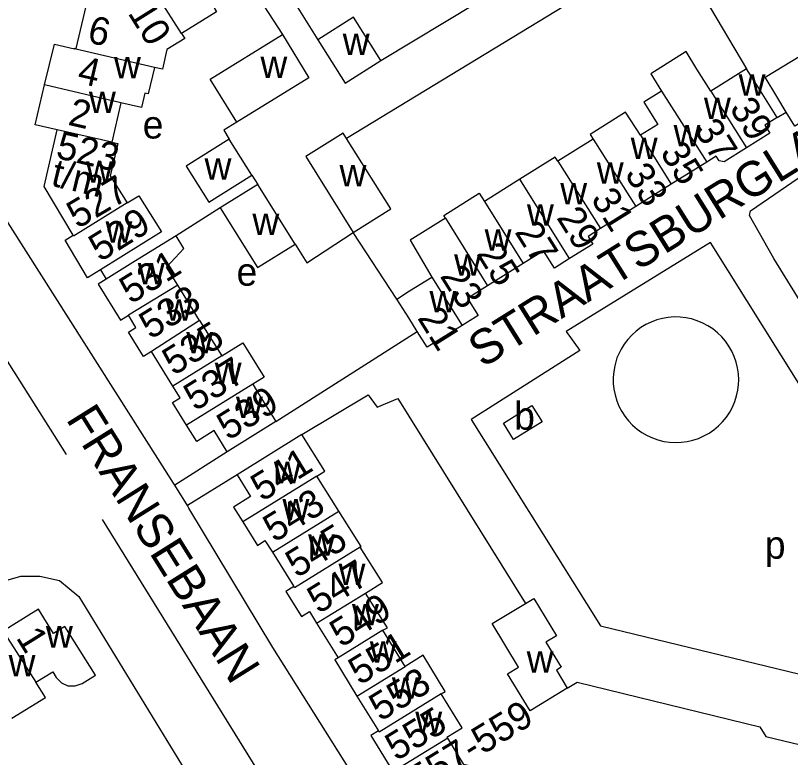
# Model space of a CAD drawing. Extents: x 157768 to 159790, y 387230 to 389604.
# Drawn here: x 158584.9 to 158696.4, y 388182.9 to 388289.6 of the extents above; entities that cross this region are included whole.
import ezdxf

# ---------------------------------------------------------------- set-up
doc = ezdxf.new("R2010")
doc.units = 0
for name, color, linetype in [('BLT_Basislijn', 7, 'Continuous'), ('BLT_Bebouwing', 7, 'Continuous'), ('BLT_Centroide', 7, 'Continuous'), ('BLT_Huisnummer', 7, 'Continuous'), ('BLT_Huisnummer_ tussenligend', 7, 'Continuous'), ('BLT_Huisnummer_reeks', 7, 'Continuous'), ('BLT_Onderverdeling_panden', 7, 'Continuous'), ('BLT_Straatnaam', 7, 'Continuous')]:
    doc.layers.add(name, color=color, linetype=linetype)

msp = doc.modelspace()

# ---------------------------------------------------------------- linework, layer by layer
at = {"layer": 'BLT_Basislijn'}
for p, q in [((158679.85, 388299.15), (158690.09, 388281.99)), ((158560.15, 388277.18), (158592.15, 388226.46)), ((158694.5, 388274.97), (158695.78, 388275.75)), ((158618.9, 388266.66), (158619.73, 388265.33)), ((158614.34, 388261.95), (158607.98, 388257.93)), ((158639.76, 388248.84), (158633.48, 388258.43)), ((158597.1, 388253.04), (158597.91, 388251.68)), ((158622.36, 388231.21), (158642.7, 388244.15)), ((158615.35, 388226.86), (158607.81, 388222.05)), ((158616.77, 388223.53), (158609.61, 388219.13)), ((158609.61, 388219.13), (158607.81, 388222.05)), ((158626.55, 388170.08), (158597.38, 388217.11))]:
    msp.add_line(p, q, dxfattribs=at)
for points in [[(158607.81, 388222.05), (158607.62, 388222.36), (158573.53, 388275.96), (158571.82, 388280.08), (158571.88, 388282.31), (158574.07, 388285.57), (158609.87, 388308.08)], [(158637.44, 388283.15), (158665.18, 388299.91), (158667.07, 388300.37), (158668.76, 388297.71), (158670.16, 388294.85), (158632.51, 388271.94)], [(158618.57, 388294.26), (158623.28, 388286.89)], [(158622.89, 388295.03), (158628.39, 388286.15)], [(158616.72, 388274.31), (158614.84, 388273.15), (158615.64, 388271.86)], [(158706.07, 388235.18), (158705.48, 388236.13), (158693.99, 388254.66), (158690.52, 388260.86), (158690.65, 388261.55), (158700.1, 388268.01)], [(158625.11, 388256.76), (158626.8, 388254.07), (158633.48, 388258.43)], [(158666.08, 388241.43), (158650.47, 388231.51), (158669.07, 388201.82), (158708.81, 388192.17), (158720.79, 388199.72), (158684.89, 388256.97)], [(158684.89, 388256.97), (158664.12, 388244.17), (158666.08, 388241.43)], [(158688.95, 388237.22), (158688.91, 388238.07), (158688.79, 388238.92), (158688.6, 388239.74), (158688.32, 388240.55), (158687.97, 388241.32), (158687.55, 388242.06), (158687.06, 388242.76), (158686.51, 388243.4), (158685.9, 388243.99), (158685.24, 388244.53), (158684.53, 388244.99), (158683.78, 388245.39), (158682.99, 388245.72), (158682.18, 388245.97), (158681.35, 388246.15), (158680.51, 388246.24), (158679.66, 388246.26), (158678.81, 388246.19), (158677.97, 388246.05), (158677.15, 388245.83), (158676.35, 388245.53), (158675.59, 388245.16), (158674.86, 388244.72), (158674.18, 388244.21), (158673.55, 388243.64), (158672.98, 388243.01), (158672.46, 388242.34), (158672.02, 388241.61), (158671.43, 388240.39)], [(158671.43, 388240.39), (158671.11, 388239.24), (158670.96, 388238.4), (158670.88, 388237.55), (158670.89, 388236.7), (158670.98, 388235.86), (158671.15, 388235.03), (158671.4, 388234.21), (158671.72, 388233.42), (158672.11, 388232.67), (158672.57, 388231.96), (158673.1, 388231.29), (158673.69, 388230.68), (158674.33, 388230.12), (158675.02, 388229.63), (158675.76, 388229.2), (158676.53, 388228.85), (158677.33, 388228.56), (158678.16, 388228.36), (158679, 388228.23), (158679.85, 388228.19), (158680.7, 388228.22), (158681.54, 388228.33), (158682.37, 388228.53), (158683.17, 388228.79), (158683.95, 388229.14), (158684.69, 388229.55), (158685.39, 388230.03), (158686.04, 388230.58), (158686.64, 388231.18), (158687.18, 388231.84), (158687.65, 388232.55), (158688.06, 388233.3), (158688.39, 388234.08), (158688.65, 388234.89), (158688.83, 388235.72), (158688.93, 388236.56), (158688.95, 388237.22)], [(158626.09, 388229.33), (158635.62, 388235.07), (158636.92, 388233.29), (158639.89, 388234.54), (158658.26, 388205.03)], [(158754.91, 388212.48), (158768.65, 388190.46), (158771.84, 388184.46), (158771.68, 388182.61), (158768.32, 388179.87), (158719.99, 388149.59), (158716.6, 388147.54), (158715.16, 388147.58), (158654.55, 388162.64), (158646.18, 388166.5), (158640.59, 388170.73), (158635.71, 388176.23), (158633.8, 388179.81), (158621.93, 388198.67), (158609.83, 388218.76), (158609.61, 388219.13)], [(158664.28, 388192.84), (158665.72, 388193.71), (158692.01, 388187.29), (158692.87, 388185.9), (158706.22, 388182.68), (158706.92, 388182.64), (158754.91, 388212.48)], [(158555.78, 388190.95), (158583.17, 388208.25), (158585.63, 388208.98), (158588.36, 388208.98), (158591.21, 388208.32), (158593.97, 388206.02), (158608.79, 388181.84), (158609.35, 388180.91)]]:
    msp.add_lwpolyline(points, dxfattribs=at)
at = {"layer": 'BLT_Bebouwing'}
for p, q in [((158690.09, 388281.99), (158684.94, 388278.76)), ((158618.9, 388266.66), (158615.64, 388271.86)), ((158668, 388271.87), (158662.91, 388268.68)), ((158684.34, 388268.56), (158679.25, 388265.37)), ((158619.73, 388265.33), (158614.34, 388261.95)), ((158625.11, 388256.76), (158619.73, 388265.33)), ((158679.25, 388265.37), (158674.16, 388262.18)), ((158674.16, 388262.18), (158669.07, 388258.99)), ((158657.94, 388253.96), (158652.78, 388250.72)), ((158611.38, 388245.75), (158614.55, 388240.65)), ((158607.52, 388236.29), (158604.43, 388241.28)), ((158622.36, 388231.21), (158615.35, 388226.86)), ((158626.09, 388229.33), (158616.77, 388223.53)), ((158631.41, 388218.29), (158628.23, 388223.37)), ((158634.6, 388213.21), (158631.41, 388218.29)), ((158621.84, 388212.39), (158624.93, 388207.46)), ((158628.2, 388202.21), (158631.3, 388197.21)), ((158640.97, 388195.97), (158637.76, 388201.18)), ((158634.02, 388191.71), (158637.1, 388186.7))]:
    msp.add_line(p, q, dxfattribs=at)
for points in [[(158593.35, 388284.85), (158593.38, 388284.96), (158593.62, 388284.91), (158595.46, 388292.86), (158602.3, 388297.17)], [(158613.32, 388290.97), (158613.8, 388290.19), (158608.79, 388287.06)], [(158637.44, 388283.15), (158633.53, 388289.39), (158628.39, 388286.15)], [(158608.79, 388287.06), (158609.24, 388286.35), (158606.67, 388284.75), (158606.02, 388281.91), (158604.87, 388282.18)], [(158616.72, 388274.31), (158612.91, 388280.5), (158623.28, 388286.89)], [(158623.28, 388286.89), (158627.09, 388280.69), (158616.72, 388274.31)], [(158589.03, 388279.66), (158590.49, 388285.51), (158593.35, 388284.85)], [(158628.39, 388286.15), (158632.3, 388279.92), (158637.44, 388283.15)], [(158684.94, 388278.76), (158682.94, 388281.94), (158681.37, 388284.44), (158676.29, 388281.26), (158677.86, 388278.75)], [(158695.78, 388275.75), (158694.43, 388277.98), (158692.75, 388280.75), (158697.9, 388283.87)], [(158604.87, 388282.18), (158603.98, 388278.36), (158603.47, 388278.48), (158602.99, 388276.42), (158600.06, 388277.1)], [(158694.5, 388274.97), (158691.84, 388279.2), (158690.09, 388281.99)], [(158590.88, 388273.18), (158587.69, 388273.9), (158589.03, 388279.66)], [(158677.86, 388278.75), (158675.32, 388277.16), (158677.31, 388273.98), (158674.83, 388272.42)], [(158701.61, 388278.29), (158702.41, 388276.97), (158697.02, 388273.7), (158695.78, 388275.75)], [(158600.06, 388277.1), (158598.74, 388271.4)], [(158674.83, 388272.42), (158672.67, 388275.73), (158667.58, 388272.54), (158668, 388271.87)], [(158694.5, 388274.97), (158692.72, 388273.85), (158693.43, 388272.72), (158690.06, 388270.6)], [(158593.18, 388258.01), (158589.01, 388265.02), (158590.88, 388273.18)], [(158615.64, 388271.86), (158609.42, 388267.96), (158612.68, 388262.76), (158618.9, 388266.66)], [(158632.51, 388271.94), (158632.03, 388272.71), (158626.64, 388269.33), (158633.48, 388258.43)], [(158633.48, 388258.43), (158638.87, 388261.81), (158632.51, 388271.94)], [(158598.74, 388271.4), (158599.59, 388271.2), (158598.52, 388266.56), (158600.94, 388262.68)], [(158690.06, 388270.6), (158686.84, 388268.59), (158686.13, 388268.75), (158685.71, 388269.42), (158684.34, 388268.56)], [(158662.91, 388268.68), (158662.54, 388269.27), (158657.45, 388266.08)], [(158657.45, 388266.08), (158652.37, 388262.89)], [(158646.77, 388260.5), (158646.54, 388260.88), (158651.62, 388264.07), (158652.37, 388262.89)], [(158600.94, 388262.68), (158602.63, 388263.68), (158605.87, 388258.5), (158597.1, 388253.04)], [(158614.34, 388261.95), (158619.72, 388253.38), (158625.11, 388256.76)], [(158646.77, 388260.5), (158641.69, 388257.31), (158644.79, 388252)], [(158669.07, 388258.99), (158667.27, 388257.85), (158667.96, 388256.75), (158664.62, 388254.66)], [(158597.1, 388253.04), (158595.25, 388251.89), (158592.04, 388257.3), (158593.18, 388258.01)], [(158607.98, 388257.93), (158602.16, 388254.32), (158597.91, 388251.68)], [(158608.22, 388250.85), (158606.61, 388253.43), (158609.11, 388256.11), (158607.98, 388257.93)], [(158664.62, 388254.66), (158662.42, 388253.28), (158660.85, 388255.79), (158657.94, 388253.96)], [(158597.91, 388251.68), (158596.77, 388250.98), (158599.99, 388245.8), (158601.13, 388246.5)], [(158639.76, 388248.84), (158641.6, 388250), (158644.79, 388252)], [(158611.38, 388245.75), (158608.22, 388250.85)], [(158652.78, 388250.72), (158651.63, 388250), (158649.92, 388248.93), (158651.45, 388246.49), (158649.15, 388245.04)], [(158642.7, 388244.15), (158641.46, 388246.12), (158639.76, 388248.84)], [(158604.43, 388241.28), (158603.3, 388240.58), (158601.12, 388244.08), (158602.21, 388244.76), (158601.13, 388246.5)], [(158649.15, 388245.04), (158644.12, 388241.89), (158642.7, 388244.15)], [(158614.55, 388240.65), (158617.61, 388242.55), (158620.67, 388237.61), (158619.02, 388236.59)], [(158609.5, 388230.67), (158607.47, 388233.93), (158608.57, 388234.61), (158607.52, 388236.29)], [(158619.02, 388236.59), (158619.72, 388235.46), (158622.36, 388231.21)], [(158615.35, 388226.86), (158613.47, 388229.9), (158610.95, 388228.33), (158609.5, 388230.67)], [(158628.23, 388223.37), (158629.37, 388224.08), (158626.09, 388229.33)], [(158616.77, 388223.53), (158618.71, 388220.43), (158616.24, 388218.88), (158617.57, 388216.76)], [(158617.57, 388216.76), (158619.68, 388213.39), (158620.78, 388214.08), (158621.84, 388212.39)], [(158634.5, 388213.15), (158634.6, 388213.21)], [(158635.24, 388206.53), (158637.69, 388208.06), (158634.5, 388213.15)], [(158624.93, 388207.46), (158623.79, 388206.75), (158626.04, 388203.17), (158627.17, 388203.87), (158628.2, 388202.21)], [(158637.76, 388201.18), (158638.39, 388201.54), (158635.24, 388206.53)], [(158664.28, 388192.84), (158658.92, 388189.6), (158655.7, 388194.92), (158657.26, 388195.86), (158653.46, 388202.13), (158658.26, 388205.03)], [(158658.26, 388205.03), (158659.47, 388205.76), (158662.71, 388200.39), (158661.21, 388199.48), (158663.4, 388195.85), (158662.71, 388195.43), (158664.28, 388192.84)], [(158596.38, 388194.72), (158592, 388201.73), (158590.36, 388200.71), (158588.17, 388204.22), (158582.86, 388200.91), (158583.12, 388200.49)], [(158631.3, 388197.21), (158630.82, 388196.92), (158634.02, 388191.71)], [(158646.13, 388192.02), (158646.72, 388192.38), (158643.53, 388197.58), (158640.97, 388195.97)], [(158587.82, 388193.68), (158590.24, 388195.19), (158590.74, 388194.37), (158591.48, 388193.61), (158592.43, 388193.18), (158593.48, 388193.17), (158594.47, 388193.52), (158596.38, 388194.72)], [(158584.35, 388188.5), (158589.18, 388191.51), (158587.82, 388193.68)], [(158647.07, 388185.64), (158646.97, 388185.8), (158649.14, 388187.13), (158646.13, 388192.02)], [(158637.1, 388186.7), (158636.01, 388186.03), (158639.28, 388180.71), (158639.49, 388180.84)], [(158653.99, 388179.86), (158653.87, 388179.89), (158654.07, 388180.73), (158649.4, 388181.85), (158647.07, 388185.64)]]:
    msp.add_lwpolyline(points, dxfattribs=at)
msp.add_lwpolyline([(158655.11, 388230.98), (158659.2, 388233.53), (158660.65, 388231.18), (158656.56, 388228.64)], close=True, dxfattribs=at)
at = {"layer": 'BLT_Onderverdeling_panden'}
for p, q in [((158608.79, 388287.06), (158602.3, 388297.17)), ((158604.87, 388282.18), (158593.35, 388284.85)), ((158600.06, 388277.1), (158589.03, 388279.66)), ((158677.86, 388278.75), (158684.34, 388268.56)), ((158684.94, 388278.76), (158690.06, 388270.6)), ((158598.74, 388271.4), (158590.88, 388273.18)), ((158668, 388271.87), (158674.16, 388262.18)), ((158674.83, 388272.42), (158679.25, 388265.37)), ((158662.91, 388268.68), (158669.07, 388258.99)), ((158664.62, 388254.66), (158657.45, 388266.08)), ((158652.37, 388262.89), (158657.94, 388253.96)), ((158646.77, 388260.5), (158652.78, 388250.72)), ((158644.79, 388252), (158649.15, 388245.04)), ((158608.22, 388250.85), (158601.13, 388246.5)), ((158611.38, 388245.75), (158604.43, 388241.28)), ((158614.55, 388240.65), (158607.52, 388236.29)), ((158619.02, 388236.59), (158609.5, 388230.67)), ((158628.23, 388223.37), (158617.57, 388216.76)), ((158621.84, 388212.39), (158631.41, 388218.29)), ((158628.2, 388202.21), (158635.24, 388206.53)), ((158637.76, 388201.18), (158631.3, 388197.21)), ((158634.02, 388191.71), (158640.97, 388195.97))]:
    msp.add_line(p, q, dxfattribs=at)
for points in [[(158600.94, 388262.68), (158593.25, 388257.89), (158593.18, 388258.01)], [(158634.5, 388213.15), (158625.04, 388207.29), (158624.93, 388207.46)], [(158583.12, 388200.49), (158583.36, 388200.67), (158587.82, 388193.68)], [(158646.13, 388192.02), (158637.2, 388186.53), (158637.1, 388186.7)], [(158647.07, 388185.64), (158639.43, 388180.94), (158639.49, 388180.84)]]:
    msp.add_lwpolyline(points, dxfattribs=at)

# ---------------------------------------------------------------- texts
at = {"layer": 'BLT_Centroide'}
for s, p in [('w', (158631.97, 388283.95)), ('w', (158599.05, 388280.59)), ('w', (158620.13, 388280.66)), ('w', (158688.94, 388278.11)), ('w', (158595.45, 388275.59)), ('w', (158683.95, 388274.73)), ('e', (158603.19, 388271.94)), ('w', (158679.58, 388270.81)), ('w', (158673.41, 388268.97)), ('w', (158595.02, 388265.59)), ('w', (158612.09, 388266)), ('w', (158668.53, 388265.44)), ('w', (158631.51, 388265.04)), ('w', (158663.27, 388262.47)), ('w', (158658.48, 388259.38)), ('w', (158618.97, 388258.06)), ('w', (158597.83, 388256.97)), ('w', (158652.39, 388255.81)), ('w', (158648, 388252.2)), ('w', (158602.48, 388250.94)), ('e', (158616.69, 388250.76)), ('w', (158644.45, 388246.94)), ('w', (158606.48, 388245.72)), ('w', (158609.45, 388241.03)), ('w', (158613.55, 388236.62)), ('w', (158616.61, 388231.72)), ('b', (158656.64, 388230.03)), ('w', (158622.07, 388222.34)), ('w', (158623.3, 388216.97)), ('w', (158626.99, 388211.91)), ('p', (158692.71, 388211.47)), ('w', (158631.37, 388207.69)), ('w', (158633.3, 388201.88)), ('w', (158589.26, 388198.69)), ('w', (158635.86, 388196.5)), ('w', (158658.44, 388195.09)), ('w', (158583.89, 388194.55)), ('w', (158639.05, 388191.31)), ('w', (158642.41, 388186.38))]:
    msp.add_text(s, height=4, dxfattribs=at).set_placement(p)
at = {"layer": 'BLT_Huisnummer'}
for s, rotation, p in [('2', 346.9763, (158592.3, 388273.94)), ('39', 302.0977, (158687.54, 388276.3)), ('33', 302.0977, (158672.45, 388266.84)), ('29', 302.0977, (158662.65, 388260.56)), ('25', 302.0977, (158651.13, 388255.38)), ('531', 31.9067, (158601.47, 388248.02)), ('21', 302.0977, (158642.63, 388246.12)), ('535', 31.8372, (158607.64, 388237.73)), ('539', 31.8389, (158615.49, 388228.4)), ('541', 31.5454, (158620.35, 388219.61)), ('545', 31.5454, (158625.35, 388208.62)), ('549', 31.7716, (158631.73, 388198.61)), ('1', 301.9591, (158584.87, 388200.11)), ('553', 31.5462, (158637.38, 388187.97))]:
    msp.add_text(s, height=4, rotation=rotation, dxfattribs=at).set_placement(p)
at = {"layer": 'BLT_Huisnummer_ tussenligend'}
for s, rotation, p in [('4', 346.9763, (158593.63, 388279.99)), ('37', 302.0977, (158682.44, 388273.22)), ('35', 302.0977, (158677.55, 388269.93)), ('31', 302.0977, (158667.59, 388263.26)), ('529', 31.9067, (158597.05, 388254.1)), ('27', 302.0977, (158656.63, 388258.49)), ('23', 302.0977, (158645.88, 388252.15)), ('533', 31.9067, (158604.31, 388242.94)), ('537', 31.8372, (158610.72, 388232.62)), ('543', 31.5454, (158622.12, 388213.73)), ('547', 31.7716, (158628.49, 388203.44)), ('551', 31.5462, (158634.4, 388193.18)), ('555', 31.545, (158639.69, 388182.28))]:
    msp.add_text(s, height=4, rotation=rotation, dxfattribs=at).set_placement(p)
at = {"layer": 'BLT_Huisnummer_reeks'}
for s, rotation, p in [('8-10', 301.9766, (158598.44, 388294.04)), ('6', 346.975, (158595.06, 388285.82)), ('523', 346.9787, (158590.54, 388269.17)), ('t/m', 346.4068, (158589.83, 388265.2)), ('527', 30.743, (158593.82, 388258.87)), ('557-559', 31.545, (158643, 388177.62))]:
    msp.add_text(s, height=4, rotation=rotation, dxfattribs=at).set_placement(p)
at = {"layer": 'BLT_Straatnaam'}
for s, rotation, p in [('STRAATSBURGLAAN', 32.026, (158652.1, 388238.84)), ('FRANSEBAAN', 301.9871, (158592.05, 388231.57))]:
    msp.add_text(s, height=5, rotation=rotation, dxfattribs=at).set_placement(p)

doc.saveas('drawing.dxf')
